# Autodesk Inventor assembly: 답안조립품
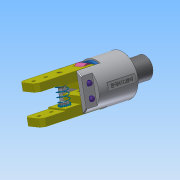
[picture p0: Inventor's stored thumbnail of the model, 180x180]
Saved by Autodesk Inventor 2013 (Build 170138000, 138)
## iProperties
Created: 2019-02
Part Number: 답안조립품
Document SubType Name: Assembly
Designer: Administrator
Author: Administrator
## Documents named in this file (11)
- C:\Users\Administrator\Desktop\490207V1023\답안조립품.iam
- C:\Users\Administrator\Desktop\490207V1023\본체.ipt
- C:\Users\Administrator\Desktop\490207V1023\E-링.ipt
- C:\Users\Administrator\Desktop\490207V1023\O-링.ipt
- C:\Users\Administrator\Desktop\490207V1023\가이드핀.ipt
- C:\Users\Administrator\Desktop\490207V1023\부시.ipt
- C:\Users\Administrator\Desktop\490207V1023\스프링.ipt
- C:\Users\Administrator\Desktop\490207V1023\평행핀 6x28.ipt
- C:\Users\Administrator\Desktop\490207V1023\피스톤.ipt
- C:\Users\Administrator\Desktop\490207V1023\핀.ipt
- C:\Users\Administrator\Desktop\490207V1023\핑거.ipt
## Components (13 placed, 6 different names)
1. E-링:1
2. O-링:1
3. 가이드핀:1
4. 피스톤:1
5. 핀:1
6. 핑거:1
7. 가이드핀:2
8. E-링:2
9. E-링:3
10. E-링:4
11. 핀:2
12. O-링:2
13. 핑거:2
